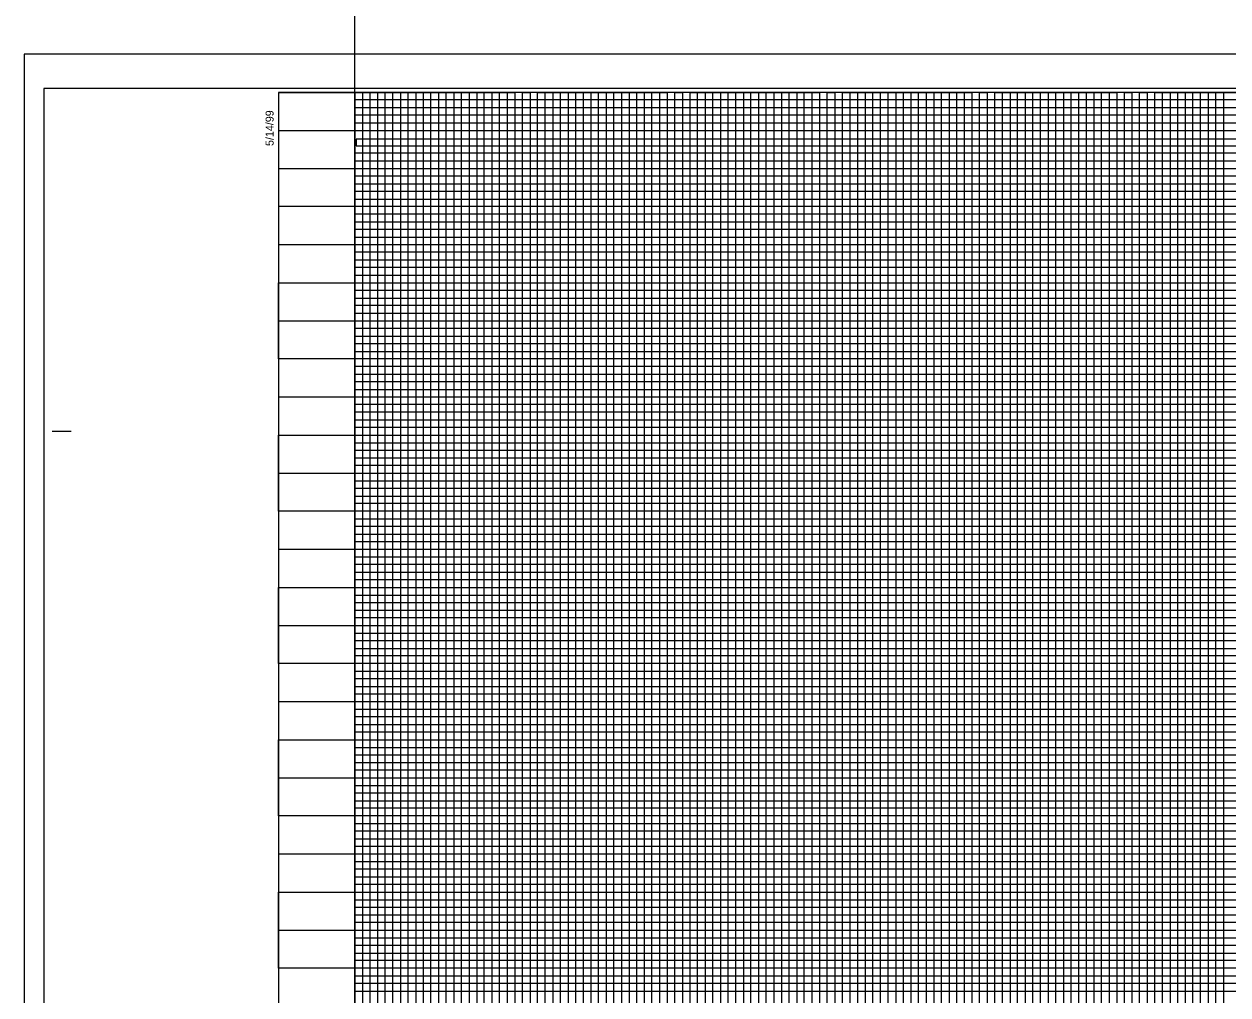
# Model space of a CAD drawing. Extents: x 2345490 to 2436403, y 465165 to 573888.
# Drawn here: x 2381523 to 2382313, y 491935 to 492573 of the extents above; entities that cross this region are included whole.
import ezdxf

# ---------------------------------------------------------------- set-up
doc = ezdxf.new("R2010")
doc.units = 0
for name, color, linetype in [('Old_Level_18', 7, 'Continuous'), ('Old_Level_41', 7, 'Continuous'), ('Old_Level_42', 7, 'Continuous'), ('Old_Level_43', 7, 'Continuous'), ('Old_Level_50', 7, 'Continuous'), ('Old_Level_51', 7, 'Continuous'), ('Old_Level_63', 7, 'Continuous')]:
    doc.layers.add(name, color=color, linetype=linetype)

msp = doc.modelspace()

# ---------------------------------------------------------------- linework, layer by layer
at = {"layer": 'Old_Level_18'}
msp.add_lwpolyline([(2383190.125, 492527.95225), (2381690.125, 492527.95225), (2381690.125, 491477.95225), (2383190.125, 491477.95225)], close=True, dxfattribs=at)
at = {"layer": 'Old_Level_41'}
msp.add_line((2381541.625, 492305.45225), (2381554.125, 492305.45225), dxfattribs=at)
for points in [[(2381690.125, 492527.95225), (2381740.125, 492527.95225), (2381740.125, 491502.95225)], [(2381765.125, 491502.95225), (2381765.125, 492527.95225), (2381815.125, 492527.95225), (2381815.125, 491502.95225), (2381865.125, 491502.95225), (2381865.125, 492527.95225), (2381915.125, 492527.95225), (2381915.125, 491502.95225), (2381965.125, 491502.95225), (2381965.125, 492527.95225), (2382015.125, 492527.95225), (2382015.125, 491502.95225), (2382065.125, 491502.95225), (2382065.125, 492527.95225), (2382115.125, 492527.95225), (2382115.125, 491502.95225), (2382165.125, 491502.95225), (2382165.125, 492527.95225), (2382215.125, 492527.95225), (2382215.125, 491502.95225), (2382265.125, 491502.95225), (2382265.125, 492527.95225), (2382315.125, 492527.95225)], [(2381790.125, 491502.95225), (2381790.125, 492527.95225), (2381840.125, 492527.95225), (2381840.125, 491502.95225)], [(2381890.125, 491502.95225), (2381890.125, 492527.95225), (2381940.125, 492527.95225), (2381940.125, 491502.95225)], [(2381990.125, 491502.95225), (2381990.125, 492527.95225), (2382040.125, 492527.95225), (2382040.125, 491502.95225)], [(2382090.125, 491502.95225), (2382090.125, 492527.95225), (2382140.125, 492527.95225), (2382140.125, 491502.95225)], [(2382190.125, 491502.95225), (2382190.125, 492527.95225), (2382240.125, 492527.95225), (2382240.125, 491502.95225)], [(2382290.125, 491502.95225), (2382290.125, 492527.95225), (2382340.125, 492527.95225)], [(2381690.125, 492477.95225), (2382990.075, 492477.95225)], [(2382990.075, 492427.95225), (2381690.125, 492427.95225), (2381690.125, 492377.90225), (2383190.125, 492377.90225)], [(2383190.125, 492352.95225), (2381690.125, 492352.95225), (2381690.125, 492402.95225), (2382990.075, 492402.95225)], [(2383190.125, 492327.95225), (2381690.125, 492327.95225), (2381690.125, 492277.95225), (2383190.125, 492277.95225)], [(2383190.125, 492252.95225), (2381690.125, 492252.95225), (2381690.125, 492302.95225), (2383190.125, 492302.95225)], [(2383190.125, 492227.95225), (2381690.125, 492227.95225), (2381690.125, 492177.95225), (2383190.125, 492177.95225)], [(2383190.125, 492127.95225), (2381690.125, 492127.95225), (2381690.125, 492077.95225), (2383190.125, 492077.95225)], [(2383190.125, 492027.95225), (2381690.125, 492027.95225), (2381690.125, 491977.95225), (2383190.125, 491977.95225)]]:
    msp.add_lwpolyline(points, dxfattribs=at)
at = {"layer": 'Old_Level_42'}
for points in [[(2382990.075, 492452.95225), (2381690.225, 492452.95225), (2381690.225, 492502.90225), (2382990.075, 492502.90225)], [(2383190.125, 492152.95225), (2381690.125, 492152.95225), (2381690.125, 492202.95225), (2383190.125, 492202.95225)], [(2383190.125, 492052.95225), (2381690.125, 492052.95225), (2381690.125, 492102.95225), (2383190.125, 492102.95225)], [(2383190.125, 491952.95225), (2381690.125, 491952.95225), (2381690.125, 492002.95225), (2383190.125, 492002.95225)]]:
    msp.add_lwpolyline(points, dxfattribs=at)
at = {"layer": 'Old_Level_43'}
for p, q in [((2383140.125, 492347.95225), (2381740.125, 492347.95225)), ((2381740.125, 492347.95225), (2381740.125, 492342.95225)), ((2381740.125, 492342.95225), (2383140.125, 492342.95225)), ((2383140.125, 492322.95225), (2381740.125, 492322.95225))]:
    msp.add_line(p, q, dxfattribs=at)
for points in [[(2381745.125, 492527.95225), (2381750.125, 492527.95225), (2381755.125, 492527.95225), (2381760.125, 492527.95225), (2381770.125, 492527.95225), (2381737.075, 492527.95225), (2381742.075, 492527.95225), (2381700.125, 492527.95225), (2381705.125, 492527.95225), (2381710.125, 492527.95225), (2381720.125, 492527.95225), (2381725.125, 492527.95225), (2381730.125, 492527.95225), (2381735.125, 492527.95225), (2381745.125, 492527.95225), (2381745.125, 491502.95225)], [(2381750.125, 491502.95225), (2381750.125, 492527.95225), (2381755.125, 492527.95225), (2381755.125, 491502.95225)], [(2381760.125, 491502.95225), (2381760.125, 492527.95225), (2381770.125, 492527.95225), (2381770.125, 491502.95225)], [(2381775.125, 491502.95225), (2381775.125, 492527.95225), (2381780.125, 492527.95225), (2381780.125, 491502.95225)], [(2381785.125, 491502.95225), (2381785.125, 492527.95225), (2381795.125, 492527.95225), (2381795.125, 491502.95225)], [(2381800.125, 491502.95225), (2381800.125, 492527.95225), (2381805.125, 492527.95225), (2381805.125, 491502.95225)], [(2381810.125, 491502.95225), (2381810.125, 492527.95225), (2381820.125, 492527.95225), (2381820.125, 491502.95225)], [(2381825.125, 491502.95225), (2381825.125, 492527.95225), (2381830.125, 492527.95225), (2381830.125, 491502.95225)], [(2381835.125, 491502.95225), (2381835.125, 492527.95225), (2381845.125, 492527.95225), (2381845.125, 491502.95225)], [(2381850.125, 491502.95225), (2381850.125, 492527.95225), (2381855.125, 492527.95225), (2381855.125, 491502.95225)], [(2381860.125, 491502.95225), (2381860.125, 492527.95225), (2381870.125, 492527.95225), (2381870.125, 491502.95225)], [(2381875.125, 491502.95225), (2381875.125, 492527.95225), (2381880.125, 492527.95225), (2381880.125, 491502.95225)], [(2381885.125, 491502.95225), (2381885.125, 492527.95225), (2381895.125, 492527.95225), (2381895.125, 491502.95225)], [(2381900.125, 491502.95225), (2381900.125, 492527.95225), (2381905.125, 492527.95225), (2381905.125, 491502.95225)], [(2381910.125, 491502.95225), (2381910.125, 492527.95225), (2381920.125, 492527.95225), (2381920.125, 491502.95225)], [(2381925.125, 491502.95225), (2381925.125, 492527.95225), (2381930.125, 492527.95225), (2381930.125, 491502.95225)], [(2381935.125, 491502.95225), (2381935.125, 492527.95225), (2381945.125, 492527.95225), (2381945.125, 491502.95225)], [(2381950.125, 491502.95225), (2381950.125, 492527.95225), (2381950.125, 492527.95225), (2381955.125, 492527.95225), (2381955.125, 491502.95225)], [(2381960.125, 491502.95225), (2381960.125, 492527.95225), (2381970.125, 492527.95225), (2381970.125, 491502.95225)], [(2381975.125, 491502.95225), (2381975.125, 492527.95225), (2381980.125, 492527.95225), (2381980.125, 491502.95225)], [(2381985.125, 491502.95225), (2381985.125, 492527.95225), (2381995.125, 492527.95225), (2381995.125, 491502.95225)], [(2382000.125, 491502.95225), (2382000.125, 492527.95225), (2382005.125, 492527.95225), (2382005.125, 491502.95225)], [(2382010.125, 491502.95225), (2382010.125, 492527.95225), (2382020.125, 492527.95225), (2382020.125, 491502.95225)], [(2382025.125, 491502.95225), (2382025.125, 492527.95225), (2382030.125, 492527.95225), (2382030.125, 491502.95225)], [(2382035.125, 491502.95225), (2382035.125, 492527.95225), (2382045.125, 492527.95225), (2382045.125, 491502.95225)], [(2382050.125, 491502.95225), (2382050.125, 492527.95225), (2382055.125, 492527.95225), (2382055.125, 491502.95225)], [(2382060.125, 491502.95225), (2382060.125, 492527.95225), (2382070.125, 492527.95225), (2382070.125, 491502.95225)], [(2382075.125, 492527.95225), (2382075.125, 491502.95225), (2382080.125, 491502.95225), (2382080.125, 492527.95225)], [(2382075.125, 492527.35225), (2382075.125, 491502.95225), (2382080.125, 491502.95225), (2382080.125, 492527.35225)], [(2382085.125, 491502.95225), (2382085.125, 492527.95225), (2382095.125, 492527.95225), (2382095.125, 491502.95225)], [(2382100.125, 491502.95225), (2382100.125, 492527.95225), (2382105.125, 492527.95225), (2382105.125, 491502.95225)], [(2382110.125, 491502.95225), (2382110.125, 492527.95225), (2382120.125, 492527.95225), (2382120.125, 491502.95225)], [(2382125.125, 491502.95225), (2382125.125, 492527.95225), (2382130.125, 492527.95225), (2382130.125, 491502.95225)], [(2382135.125, 491502.95225), (2382135.125, 492527.95225), (2382145.125, 492527.95225), (2382145.125, 491502.95225)], [(2382150.125, 491502.95225), (2382150.125, 492527.95225), (2382155.125, 492527.95225), (2382155.125, 491502.95225)], [(2382160.125, 491502.95225), (2382160.125, 492527.95225), (2382170.125, 492527.95225), (2382170.125, 491502.95225)], [(2382175.125, 491502.95225), (2382175.125, 492527.95225), (2382180.125, 492527.95225), (2382180.125, 491502.95225)], [(2382185.125, 491502.95225), (2382185.125, 492527.95225), (2382195.125, 492527.95225), (2382195.125, 491502.95225)], [(2382200.125, 491502.95225), (2382200.125, 492527.95225), (2382205.125, 492527.95225), (2382205.125, 491502.95225)], [(2382210.125, 491502.95225), (2382210.125, 492527.95225), (2382220.125, 492527.95225), (2382220.125, 491502.95225)], [(2382225.125, 492527.95225), (2382225.125, 491502.95225), (2382230.125, 491502.95225), (2382230.125, 492527.95225), (2382235.125, 492527.95225), (2382235.125, 491502.95225), (2382245.125, 491502.95225), (2382245.125, 492527.95225), (2382250.125, 492527.95225), (2382250.125, 491502.95225), (2382255.125, 491502.95225), (2382255.125, 492527.95225), (2382260.125, 492527.95225), (2382260.125, 491502.95225)], [(2382270.125, 491502.95225), (2382270.125, 492527.95225), (2382275.125, 492527.95225), (2382275.125, 491502.95225), (2382280.125, 491502.95225), (2382280.125, 492527.95225), (2382285.125, 492527.95225), (2382285.125, 491502.95225), (2382295.125, 491502.95225), (2382295.125, 492527.95225), (2382300.125, 492527.95225), (2382300.125, 491502.95225), (2382300.125, 491502.95225), (2382305.125, 491502.95225), (2382305.125, 492527.95225), (2382310.125, 492527.95225), (2382310.125, 491502.95225), (2382320.125, 491502.95225)], [(2382990.075, 492522.95225), (2381740.125, 492522.95225), (2381740.125, 492517.95225), (2382990.075, 492517.95225)], [(2382990.075, 492512.95225), (2381740.125, 492512.95225), (2381740.125, 492507.95225), (2382990.075, 492507.95225)], [(2382990.075, 492497.20225), (2381741.125, 492497.20225), (2381741.125, 492492.95225), (2382990.075, 492492.95225)], [(2382990.075, 492487.95225), (2381740.125, 492487.95225), (2381740.125, 492482.95225), (2382990.075, 492482.95225)], [(2382990.075, 492472.95225), (2381740.125, 492472.95225), (2381740.125, 492467.95225), (2382990.075, 492467.95225)], [(2382990.075, 492462.95225), (2381740.125, 492462.95225), (2381740.125, 492457.95225), (2382990.075, 492457.95225)], [(2382990.075, 492447.95225), (2381740.125, 492447.95225), (2381740.125, 492442.95225), (2382990.075, 492442.95225)], [(2382990.075, 492437.95225), (2381740.125, 492437.95225), (2381740.125, 492432.95225), (2382990.075, 492432.95225)], [(2382990.075, 492422.95225), (2381740.125, 492422.95225), (2381740.125, 492417.95225), (2382990.075, 492417.95225)], [(2382990.075, 492412.95225), (2381740.125, 492412.95225), (2381740.125, 492407.95225), (2382990.075, 492407.95225)], [(2382990.075, 492397.95225), (2381740.125, 492397.95225), (2381740.125, 492392.95225), (2382990.075, 492392.95225)], [(2383140.125, 492387.95225), (2381740.125, 492387.95225), (2381740.125, 492387.95225), (2381740.125, 492367.95225), (2383140.125, 492367.95225)], [(2381740.125, 492382.95225), (2383140.125, 492382.95225)], [(2383140.125, 492372.95225), (2381740.125, 492372.95225)], [(2383140.125, 492362.95225), (2381740.125, 492362.95225), (2381740.125, 492357.95225), (2383140.125, 492357.95225)], [(2383140.125, 492337.95225), (2381740.125, 492337.95225), (2381740.125, 492332.95225), (2383140.125, 492332.95225)], [(2383140.125, 492317.95225), (2381740.125, 492317.95225), (2381740.125, 492312.95225), (2383140.125, 492312.95225)], [(2383140.125, 492307.95225), (2381740.125, 492307.95225)], [(2381740.125, 492297.95225), (2383140.125, 492297.95225)], [(2383140.125, 492292.95225), (2381740.125, 492292.95225), (2381740.125, 492287.95225), (2383140.125, 492287.95225)], [(2383140.125, 492282.95225), (2381740.125, 492282.95225), (2381740.125, 492272.95225), (2383140.125, 492272.95225)], [(2383140.125, 492267.95225), (2381740.125, 492267.95225), (2381740.125, 492262.95225), (2383140.125, 492262.95225)], [(2383140.125, 492257.95225), (2381740.125, 492257.95225), (2381740.125, 492247.95225), (2383140.125, 492247.95225)], [(2383140.125, 492242.95225), (2381740.125, 492242.95225), (2381740.125, 492237.95225), (2383140.125, 492237.95225)], [(2383140.125, 492232.95225), (2381740.125, 492232.95225), (2381740.125, 492222.95225), (2383140.125, 492222.95225)], [(2383140.125, 492217.95225), (2381740.125, 492217.95225), (2381740.125, 492212.95225), (2383140.125, 492212.95225)], [(2383140.125, 492207.95225), (2381740.125, 492207.95225), (2381740.125, 492197.95225), (2383140.125, 492197.95225)], [(2383140.125, 492192.95225), (2381740.125, 492192.95225), (2381740.125, 492187.95225), (2383140.125, 492187.95225)], [(2383140.125, 492182.95225), (2381740.125, 492182.95225), (2381740.125, 492172.95225), (2383140.125, 492172.95225)], [(2383140.125, 492167.95225), (2381740.125, 492167.95225), (2381740.125, 492162.95225), (2383140.125, 492162.95225)], [(2383140.125, 492157.95225), (2381740.125, 492157.95225), (2381740.125, 492147.95225), (2383140.125, 492147.95225)], [(2383140.125, 492142.95225), (2381740.125, 492142.95225), (2381740.125, 492137.95225), (2383140.125, 492137.95225)], [(2383140.125, 492132.95225), (2381740.125, 492132.95225), (2381740.125, 492122.95225), (2383140.125, 492122.95225)], [(2383140.125, 492117.95225), (2381740.125, 492117.95225), (2381740.125, 492112.95225), (2383140.125, 492112.95225)], [(2383140.125, 492107.95225), (2381740.125, 492107.95225), (2381740.125, 492097.95225), (2383140.125, 492097.95225)], [(2383140.125, 492092.95225), (2381740.125, 492092.95225), (2381740.125, 492087.95225), (2383140.125, 492087.95225)], [(2383140.125, 492082.95225), (2381740.125, 492082.95225), (2381740.125, 492072.95225), (2383140.125, 492072.95225)], [(2383140.125, 492067.95225), (2381740.125, 492067.95225), (2381740.125, 492062.95225), (2383140.125, 492062.95225)], [(2383140.125, 492057.95225), (2381740.125, 492057.95225), (2381740.125, 492047.95225), (2383140.125, 492047.95225)], [(2383140.125, 492042.95225), (2381740.125, 492042.95225), (2381740.125, 492037.95225), (2383140.125, 492037.95225)], [(2383140.125, 492032.95225), (2381740.125, 492032.95225), (2381740.125, 492022.95225), (2383140.125, 492022.95225)], [(2383140.125, 492017.95225), (2381740.125, 492017.95225), (2381740.125, 492012.95225), (2383140.125, 492012.95225)], [(2383140.125, 492007.95225), (2381740.125, 492007.95225)], [(2381740.125, 491997.95225), (2383140.125, 491997.95225)], [(2383140.125, 491992.95225), (2381740.125, 491992.95225), (2381740.125, 491987.95225), (2383140.125, 491987.95225)], [(2383140.125, 491982.95225), (2381740.125, 491982.95225), (2381740.125, 491972.95225), (2383140.125, 491972.95225)], [(2383140.125, 491967.95225), (2381740.125, 491967.95225), (2381740.125, 491962.95225), (2383140.125, 491962.95225)], [(2383140.125, 491957.95225), (2381740.125, 491957.95225), (2381740.125, 491947.95225), (2383140.125, 491947.95225)], [(2383140.125, 491942.95225), (2381740.125, 491942.95225), (2381740.125, 491937.95225), (2383140.125, 491937.95225)]]:
    msp.add_lwpolyline(points, dxfattribs=at)
at = {"layer": 'Old_Level_50'}
msp.add_lwpolyline([(2383202.625, 492530.50225), (2381536.125, 492530.50225), (2381536.125, 491475.40225), (2383202.625, 491475.40225)], close=True, dxfattribs=at)
at = {"layer": 'Old_Level_51'}
msp.add_lwpolyline([(2383207.125, 492552.95225), (2381523.125, 492552.95225), (2381523.125, 491452.95225), (2383207.125, 491452.95225)], close=True, dxfattribs=at)
at = {"layer": 'Old_Level_63'}
msp.add_line((2381740.125, 491502.95225), (2381740.125, 494002.95225), dxfattribs=at)

# ---------------------------------------------------------------- texts
at = {"layer": 'Old_Level_41'}
msp.add_text('5/14/99', height=5.25, rotation=90, dxfattribs=at).set_placement((2381686.875, 492492.75225))

doc.saveas('drawing.dxf')
